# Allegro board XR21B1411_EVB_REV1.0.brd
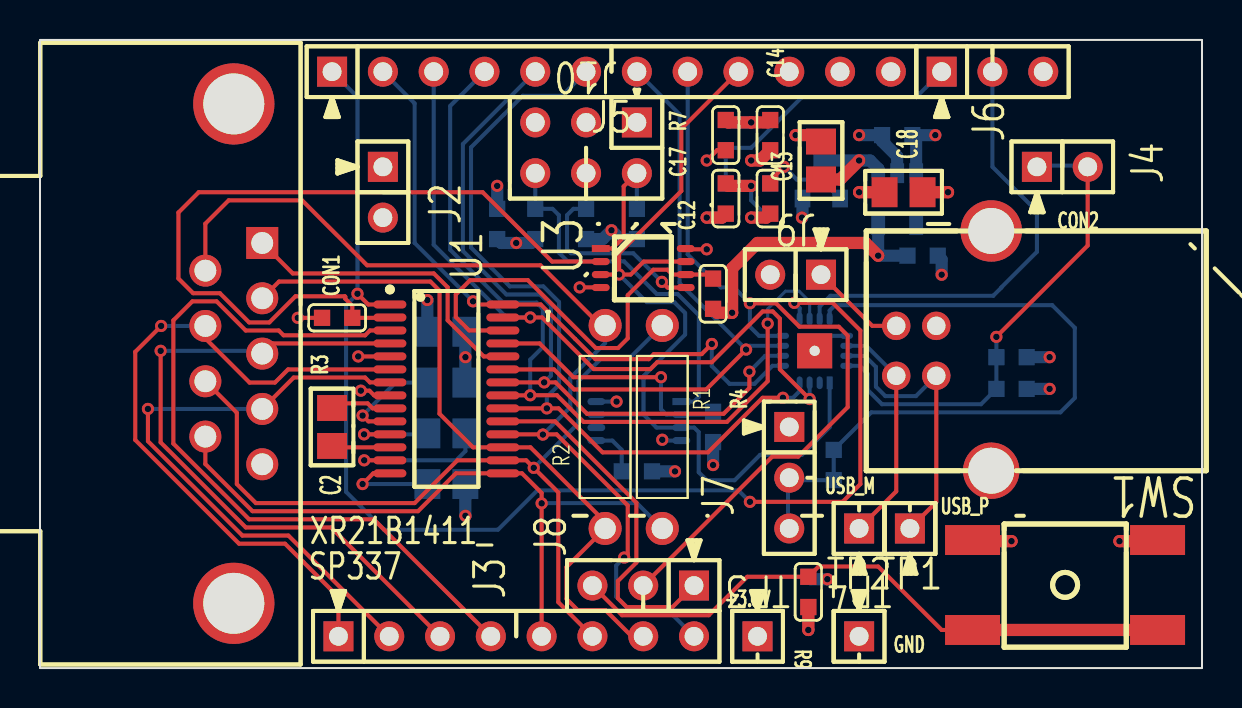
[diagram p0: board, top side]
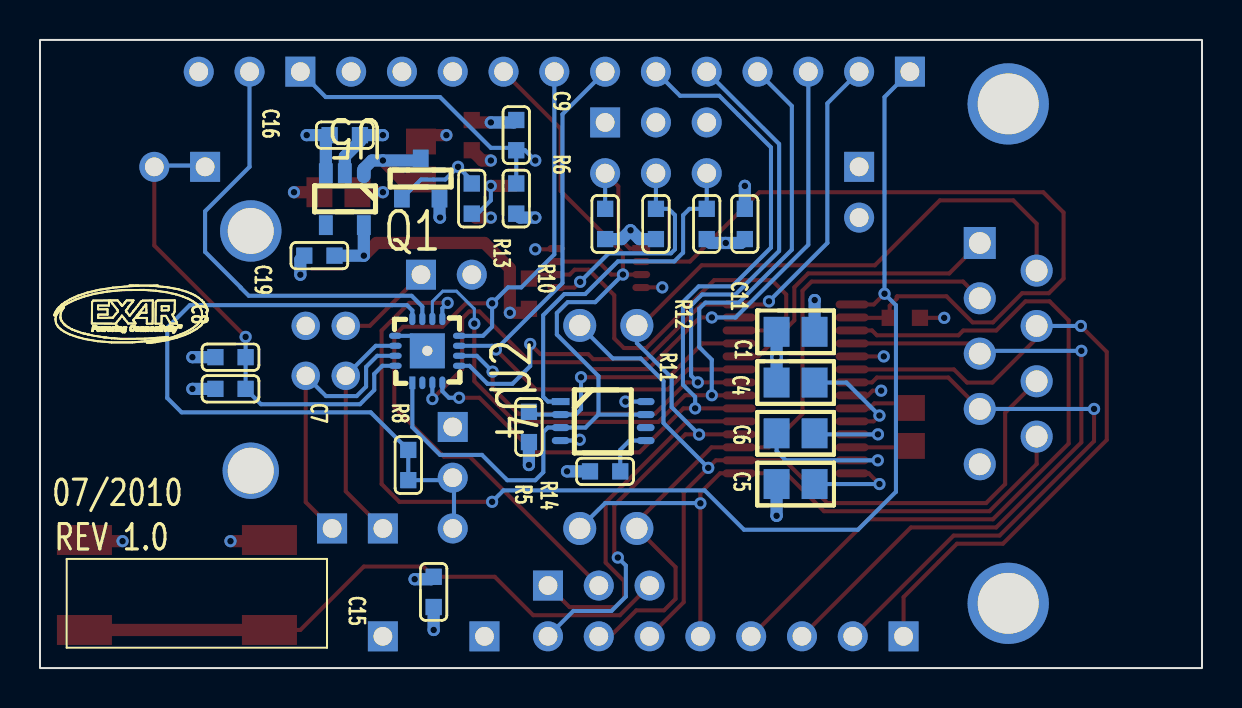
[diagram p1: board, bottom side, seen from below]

Outline 58.1 x 31.43 mm; copper layers: TOP, L2 GND, L3 PWR, BOTTOM. Coordinates in mm from the lower left corner of the outline.
Outline path: rectangle 0,0 58.1,31.43

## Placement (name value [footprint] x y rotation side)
C1  1U-0603_XXXXXX-ND  [CR0805]  20.32 16.83 180 bottom
C2  100p-0603_399-1095-1-ND  [CR0805]  14.61 12.06 90 top
C4  100p-0603_399-1095-1-ND  [CR0805]  20.32 14.29 180 bottom
C5  100p-0603_399-1095-1-ND  [CR0805]  20.32 9.21 180 bottom
C6  100p-0603_399-1095-1-ND  [CR0805]  20.32 11.75 180 bottom
C7  100n_0603_399-1095-1-ND  [CR0603]  48.58 13.97 180 bottom
C8  100n_0603_399-1095-1-ND  [CR0603]  48.58 15.56 180 bottom
C9  100n_0603_399-1095-1-ND  [CR0603]  34.29 26.67 90 bottom
C11  100n_0603_399-1095-1-ND  [CR0603]  22.86 22.23 270 bottom
C12  100n_0603_399-1095-1-ND  [CR0603]  36.51 23.5 90 top
C13  10U_0805, 10V_399-4925-1-ND  [CR0805]  39.05 25.4 90 top
C14  100n_0603_399-1095-1-ND  [CR0603]  36.51 26.67 90 top
C15  100n_0603_399-1095-1-ND  [CR0603]  38.42 3.81 270 bottom
C16  1U-0805,16V_PCC2249TR-ND  [CR0603]  42.86 26.67 0 bottom
C17  100n_0603_399-1095-1-ND  [CR0603]  34.29 23.5 90 top
C18  1U-0805,16V_PCC2249TR-ND  [CR0805]  43.18 23.81 180 top
C19  100n_0603_399-1095-1-ND  [CR0603]  44.13 20.64 0 bottom
CON1  CONNECTOR_DB9_182-709ME-ND  [DSUB9_MALE]  11.11 21.27 270 top
CON2  USB B-_A31725-ND  [USB_B_TYPE_CON_1]  43.81 15.88 90 top
J2  2x1 .1  Header_PEC02SAAN  [HDR254S3-1X2]  17.14 25.08 270 top
J3  CON2_7  [HDR254S3-1X8]  14.92 1.59 0 top
J4  2x1 .1  Header_PEC02SAAN  [HDR254S3-1X2]  49.85 25.08 0 top
J5  12x1 .1  _Header_PEC012SAAN  [HDR254S3-1X12]  14.61 29.84 0 top
J6  3x1 .1  Header_PEC03SAAN  [HDR254S3-1X3]  45.09 29.84 0 top
J7  3x1 .1  Header_PEC03SAAN  [HDR254S3-1X3]  37.47 12.06 270 top
J8  3x1 .1  Header_PEC03SAAN  [HDR254S3-1X3]  32.7 4.13 180 top
J9  2x1 .1  Header_PEC02SAAN  [HDR254S3-1X2]  39.05 19.68 180 top
J10  CON6A_PEC03DAAN  [HDR254M-2X3]  29.84 27.3 180 top
NOREF  -  []  0 31.43 0 top
NOREF#2  -  []  0 0 90 top
NOREF#3  -  []  57.4 16.26 180 bottom
Q1  SI2333DS-T1-E3-SOT-23  [SOT_23]  40.01 23.5 180 bottom
R1  120_0603  [RES400]  31.11 6.99 0 top
R2  120_0603  [RES400]  28.26 17.14 180 top
R3  470K-0603_311-470KGRCT-ND  [CR0603]  14.86 17.53 180 top
R4  470K-0603_311-470KGRCT-ND  [CR0603]  33.66 18.73 270 top
R5  470K-0603_311-470KGRCT-ND  [CR0603]  33.66 12.06 270 bottom
R6  3.3K-0603  [CR0603]  34.29 23.5 90 bottom
R7  4.7K-0603  [CR0603]  34.29 26.67 90 top
R8  ZERO-0603  [CR0603]  39.69 10.16 90 bottom
R9  47K-0603_311-47KGRCT-ND  [CR0603]  38.42 3.81 270 top
R10  47K-0603_311-47KGRCT-ND  [CR0603]  29.84 22.23 270 bottom
R11  47K-0603_311-47KGRCT-ND  [CR0603]  27.3 22.23 270 bottom
R12  47K-0603_311-47KGRCT-ND  [CR0603]  24.77 22.23 270 bottom
R13  40.2K-0603_311-40.2KGRCT-ND  [CR0603]  36.51 23.5 270 bottom
R14  47K-0603_311-47KGRCT-ND  [CR0603]  29.84 9.84 0 bottom
SW1  PB SW_101-0164-EV  [TACT_SMD_SWITCH_SWITRONICS]  55.88 1.91 180 top
TP1  PEC01SAAN  [HDR254S3-1X1]  43.5 6.99 0 top
TP2  PEC01SAAN  [HDR254S3-1X1]  40.96 6.99 0 top
TP3  PEC01SAAN  [HDR254S3-1X1]  35.88 1.59 180 top
TP4  PEC01SAAN  [HDR254S3-1X1]  40.96 1.59 180 top
U1  SP337_TSSOP  [TSSOP65MM_28P]  20.32 13.97 270 top
U2  XR21B1411IL16-QFN16  [QFN_16_3X3_MM]  38.73 15.88 90 bottom
U3  SN74LVC2G66DCT  [SSOP_8]  28.04 20.99 270 top
U4  SN74LVC2G66DCT  [SSOP_8]  32.07 13.34 270 bottom
U5  SP6260GEK-L/TR150MA  [SOT_23_5]  41.91 24.77 0 bottom

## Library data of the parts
C1 C2 C4-C9 C11-C19 = CAP NP
CON1 = CONNECTOR_DB9_0
CON2 = USB B-Type Connector
J2 J4 J9 = CON2: User Part Number: pn; Tolerance: RichardLC
J3 = CON2_7: User Part Number: pn; Tolerance: RichardLC
J5 = CON2_1: User Part Number: pn; Tolerance: RichardLC
J6-J8 = CON3: User Part Number: pn; Tolerance: RichardLC
J10 = CON6A: User Part Number: pn; Tolerance: RichardLC
Q1 = Si2333DS
R1 R2 = R_0: Tolerance: ***; User Part Number: ***; room: MASTER_CH1
R3-R5 = R_0: room: MASTER_CH1
R6-R14 = R
SW1 = SW PUSHBUTTON-SPST-2
TP1-TP4 = TP: User Part Number: pn; Tolerance: RichardLC
U1 = SP302_9: User Part Number: pn; Tolerance: RichardLC; room: MASTER_CH9
U2 = XR21V1410_7
U3 U4 = SN74LVC2G66DCT_0
U5 = SP6669_0

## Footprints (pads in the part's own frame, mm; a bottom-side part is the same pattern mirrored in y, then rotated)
CR0603
  rect 0.813x0.813 smd: 1(-0.756,0) 2(0.756,0)
CR0805
  rect 1.295x1.499 smd: 1(-0.95,0) 2(0.95,0)
DSUB9_MALE
  rect 1.6x1.6 hole 1.092: 1(0,0)
  round 1.6 hole 1.092: 2(2.769,0) 3(5.537,0) 4(8.306,0) 5(11.074,0) 6(1.384,-2.845) 7(4.153,-2.845) 8(6.921,-2.845) 9(9.69,-2.845)
  round 4.064 hole 3.048: MH1(-6.96,-1.422) MH2(18.034,-1.422)
HDR254M-2X3
  rect 1.5x1.5 hole 0.94: 1(0,0)
  round 1.5 hole 0.94: 2(0,2.54) 3(2.54,0) 4(2.54,2.54) 5(5.08,0) 6(5.08,2.54)
HDR254S3-1X1
  rect 1.5x1.5 hole 0.94: 1(0,0)
HDR254S3-1X2
  rect 1.5x1.5 hole 0.94: 1(0,0)
  round 1.5 hole 0.94: 2(2.54,0)
HDR254S3-1X3
  rect 1.5x1.5 hole 0.94: 1(0,0)
  round 1.5 hole 0.94: 2(2.54,0) 3(5.08,0)
HDR254S3-1X8
  rect 1.5x1.5 hole 0.94: 1(0,0)
  round 1.5 hole 0.94: 2(2.54,0) 3(5.08,0) 4(7.62,0) 5(10.16,0) 6(12.7,0) 7(15.24,0) 8(17.78,0)
HDR254S3-1X12
  rect 1.5x1.5 hole 0.94: 1(0,0)
  round 1.5 hole 0.94: 2(2.54,0) 3(5.08,0) 4(7.62,0) 5(10.16,0) 6(12.7,0) 7(15.24,0) 8(17.78,0) 9(20.32,0) 10(22.86,0) 11(25.4,0) 12(27.94,0)
QFN_16_3X3_MM
  rect 0.635x0.305 smd: 1(-1.6,0.749)
  oval 0.635x0.305 smd: 2(-1.6,0.249) 3(-1.6,-0.251) 4(-1.6,-0.752) 9(1.6,-0.752) 10(1.6,-0.251) 11(1.6,0.249) 12(1.6,0.749)
  oval 0.305x0.635 smd: 5(-0.749,-1.6) 6(-0.249,-1.6) 7(0.251,-1.6) 8(0.752,-1.6) 13(0.752,1.6) 14(0.251,1.6) 15(-0.249,1.6) 16(-0.749,1.6)
  rect 1.753x1.753 hole 0.508: 17(0,0)
RES400
  round 1.651 hole 1.067: 1(0,0) 2(0,10.16)
SOT_23
  rect 0.787x0.889 smd: 1(0,0) 2(1.88,0) 3(0.94,2.007)
SOT_23_5
  oval 0.691x0.991 smd: 1(0,0)
  rect 0.691x0.991 smd: 2(0.95,0) 3(1.9,0) 4(1.9,2.601) 5(0,2.601)
SSOP_8
  rect 0.356x0.889 smd: 1(0,0)
  oval 0.356x0.889 smd: 2(0.65,0) 3(1.3,0) 4(1.951,0) 5(1.951,4.249) 6(1.3,4.249) 7(0.65,4.249) 8(0,4.249)
TACT_SMD_SWITCH_SWITRONICS
  rect 2.751x1.499 smd: 1(0,0) 2(9.251,0) 3(0,-4.501) 4(9.251,-4.501)
TSSOP65MM_28P
  oval 0.4x1.65 smd: 1(-4.225,-2.825) 2(-3.575,-2.825) 3(-2.925,-2.825) 4(-2.275,-2.825) 5(-1.625,-2.825) 6(-0.975,-2.825) 7(-0.325,-2.825) 8(0.325,-2.825) 9(0.975,-2.825) 10(1.625,-2.825) 11(2.275,-2.825) 12(2.925,-2.825) 13(3.575,-2.825) 14(4.225,-2.825) 15(4.225,2.825) 16(3.575,2.825) 17(2.925,2.825) 18(2.275,2.825) 19(1.625,2.825) 20(0.975,2.825) 21(0.325,2.825) 22(-0.325,2.825) 23(-0.975,2.825) 24(-1.625,2.825) 25(-2.275,2.825) 26(-2.925,2.825) 27(-3.575,2.825) 28(-4.225,2.825)
USB_B_TYPE_CON_1
  round 1.422 hole 0.919: 1(1.25,1.001) 2(-1.25,1.001) 3(-1.25,-1.001) 4(1.25,-1.001)
  round 3.073 hole 2.299: 5(5.999,-3.749)
  round 2.819 hole 2.299: 6(-5.999,-3.749)

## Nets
+3.3V: C11.2 C15.2 C18.2 C19.1 J2.1 J7.3 R4.2 R5.2 R9.2 R10.2 R11.2 R12.2 R14.2 TP3.1 U3.8(VCC) U4.8(VCC) U5.5(VOUT)
GND: C1.1 C4.1 C5.1 C7.1 C8.1 C9.2 C11.1 C13.2 C14.2 C15.1 C16.1 C17.2 C18.1 C19.2 CON1.5 CON1.MH1 CON1.MH2 CON2.4(GND) CON2.5(SH1) CON2.6(SH2) J5.11 J5.12 J6.3 J10.1 J10.3 J10.5 R3.2 R7.2 R13.2 SW1.3 SW1.4 TP4.1 U1.8(GND) U2.13(GND_13) U2.17(E_PAD) U3.4(GND) U4.4(GND) U5.2(GND)
VBUS_SENSE: J6.2 U2.11(VBUS_SENSE)
VCC_USB: C13.1 C14.1 C16.2 C17.1 J4.1 Q1.3(D) R6.1 U5.1(VIN) U5.3(CE)
VCC_USB_VBUS: C12.1 J9.2 Q1.2(S)
CD#: J5.7 U1.23(R5_OUT) U2.7(GPIO1/CD#)
CTS: CON1.8 J3.6 R1.2 U1.16(R2_IN)
CTS#: J5.6 U1.20(R2_OUT) U2.4(GPIO4/CTS#)
DCD: CON1.1 U1.24(R5_IN)
DSR: CON1.6 J3.8 R2.1 U1.18(R4_IN)
DSR#: J5.5 U1.22(R4_OUT) U2.6(GPIO2/DSR#)
DTR: CON1.4 J3.2 U1.7(T2_OUT)
DTR#: J5.2 U1.28(T2_IN) U2.5(GPIO3/DTR#)
RD: CON1.2 J3.7 R2.2 U1.17(R3_IN)
RI: CON1.9 J3.5 R1.1 U1.15(R1_IN)
RI#: J5.8 J8.2 U2.8(GPIO0/RI#)
RS232#_RS485: R5.1 U1.25(RS232#_RS485) U4.2(1B)
RTS: CON1.7 J3.1 U1.6(T1_OUT)
RTS#: J5.3 U1.27(T1_IN) U2.3(GPIO5/RTS#)
RX: J5.4 U1.21(R3_OUT) U2.10(RX)
RX_EN#: R4.1 U1.26(RX_EN#) U3.6(2B)
SUSPEND#: J5.9 U2.1(LOWPOWER) U3.3(2C) U3.7(1C) U4.3(2C) U4.7(1C)
TD: CON1.3 J3.3 U1.4(T3_OUT)
TRANS_RI#: J8.1 U1.19(R1_OUT)
TX: J5.1 U1.1(T3_IN) U2.9(TX)
TX_EN: R3.1 U1.2(TX_EN) U3.2(1B)
USB_DM: CON2.2(DM) TP2.1 U2.14(USBD_M)
USB_DP: CON2.3(DP) TP1.1 U2.15(USBD_P)
VIO_REF: C1.2 J2.2 J5.10 J7.1 U1.5(VCC)
N17094617: J8.3 R9.1 SW1.1 SW1.2
N17260408: C7.2 C8.2 J4.2 U2.16(VCC)
N17360914: R14.1 U4.5(2A)
N17372035: J10.2 R10.1 U3.1(1A)
N17372732: J10.4 R11.1 U3.5(2A)
N17428845: CON2.1(V_BUS) J9.1
N17428937: C12.2 Q1.1(G) R13.1
N17497408: J10.6 R12.1 U4.1(1A)
N17687931: J7.2 R8.1
N17694114: C9.1 J6.1 R6.2 R7.1
N17722908: R8.2 U2.12(VIO_REF)
N17796579: J3.4 U1.3(T4_OUT)
N17796703: C4.2 U1.10(V+)
N17796705: C5.2 U1.14(V-)
N17796729: C2.2 U1.9(C1(+))
N17796733: C2.1 U1.12(C1(-))
N17796737: C6.1 U1.13(C2(-))
N17796741: C6.2 U1.11(C2(+))

Pads without a net: U2 2; U4 6; U5 4

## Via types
v1: diameter 0.61, hole 0.33, TOP to BOTTOM, 68 vias

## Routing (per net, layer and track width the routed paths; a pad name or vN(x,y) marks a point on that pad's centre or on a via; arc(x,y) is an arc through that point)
+3.3V: length 27.3
  TOP w0.203: U3.8 32.33,20.95 v1(33.34,20.95)
  TOP w0.61: v1(38.42,1.91) R9.2 ; v1(41.91,20.64) 41.27,21.27 35.88,21.27 34.61,20 v1(34.61,17.78) 33.85,17.78 R4.2 ; C18.2 v1(40.96,23.81)
  BOTTOM w0.203: U4.8 v1(28.83,13.34)
  BOTTOM w0.61: R10.2 29.01,21.47 v1(28.57,21.91) 28.14,21.47 R11.2 ; U5.5 v1(41.91,20.64) C19.1 ; C11.2 23.06,21.27 v1(23.81,21.27) 24.57,21.27 R12.2 ; v1(31.75,9.84) R14.2 ; v1(38.42,1.91) R9.2 ; R5.2 v1(33.66,10.16)
GND: length 33.2
  TOP w0.203: R3.2 v1(12.89,17.53) ; U3.4 28.03,19.05 v1(26.99,19.05) ; U1.8 16.71,13.64 16.47,13.88 v1(16.04,13.88)
  TOP w0.61: SW1.4 46.69,6.35 v1(48.58,6.35) ; R7.2 34.41,27.3 v1(35.56,27.3) 36.39,27.3 C14.2 ; v1(53.98,6.35) 55.82,6.35 SW1.3 ; C17.2 34.41,24.13 v1(35.56,24.13) ; v1(45.4,23.81) C18.1 ; v1(37.78,26.67) 38.73,26.67 C13.2
  BOTTOM w0.203: v1(35.56,24.13) 35.56,23.4 36.23,22.74 R13.2 ; U2.13 39.49,16.63 U2.17 ; v1(31.11,11.42) 31.16,11.38 U4.4
  BOTTOM w0.61: R7.2 34.41,27.3 v1(35.56,27.3) ; C4.1 21.27,15.55 v1(21.27,15.56) 21.27,15.56 C1.1 ; v1(50.48,15.56) C8.1 ; C15.1 38.54,4.45 v1(39.37,4.45) ; v1(21.27,7.62) 21.27,7.62 C5.1 ; v1(45.09,19.68) 45.09,20.44 C19.2 ; v1(40.96,26.67) C16.1 42.11,26.36 42.86,25.61 U5.2 ; v1(22.86,24.13) C11.1 ; v1(50.48,13.97) C7.1
VBUS_SENSE: length 22.6
  BOTTOM w0.203: U2.11 38.98,18.09 39.52,18.63 47.66,18.63 48.07,19.04 48.07,19.05 49.85,20.83 49.85,22.86 47.62,25.08 J6.2
VCC_USB: length 11.9
  TOP w0.61: C14.1 36,25.4 v1(35.56,25.4) ; C13.1 40.01,24.45 v1(40.96,25.4) ; C17.1 34.09,22.54 v1(33.34,22.54)
  BOTTOM w0.61: U5.3 43.81,26.48 C16.2 v1(44.77,26.67) ; Q1.3 39.17,25.4 v1(40.96,25.4) 41.5,25.4 41.91,24.99 U5.1 ; C17.1 34.09,22.54 v1(33.34,22.54)
VCC_USB_VBUS: length 2
  TOP w0.61: C12.1 36.32,22.54 v1(35.56,22.54)
  BOTTOM w0.61: Q1.2 38.13,22.57 v1(38.1,22.54)
CD#: length 31.5
  TOP w0.203: v1(35.31,15.94) 33.31,13.94 26.71,13.94 25.7,14.95 U1.23
  BOTTOM w0.203: J5.7 31.98,27.71 31.98,19.27 v1(35.31,15.94) 35.49,16.13 U2.7
CTS: length 42.3
  TOP w0.203: CON1.8 9.84,12.78 9.84,9.21 10.79,8.26 18.73,8.26 20.87,10.39 U1.16 24.31,10.39 v1(24.69,10.02) 25.92,8.79 25.92,3.29 J3.6
  BOTTOM w0.203: v1(24.69,10.02) 26.92,12.26 26.92,14.35 28.06,15.49 29.46,15.49 R1.2
CTS#: length 40.9
  TOP w0.203: U1.20 v1(25.34,12.99) 25.93,12.99 28.13,10.79 33.4,10.79 36.13,13.53 v1(37.15,13.53)
  BOTTOM w0.203: U2.4 37.98,13.85 37.66,13.53 v1(37.15,13.53) ; J5.6 26.1,28.64 24.13,28.64 23.18,27.68 21.55,26.06 21.55,21.04 23.49,19.1 25.17,19.1 25.95,18.31 25.95,14.18 25.34,13.57 v1(25.34,12.99)
DCD: length 15.4
  TOP w0.203: U1.24 22.19,15.6 20.38,17.4 20.38,19.05 19.69,19.75 12.64,19.75 CON1.1
DSR: length 49.4
  TOP w0.203: CON1.6 8.27,22.24 9.44,23.41 13.11,23.41 16.36,20.15 25.02,20.15 28.03,17.14 R2.1 ; 25.14,11.69 v1(25.15,11.68) ; 25.14,11.69 25.83,11.69 29.39,8.14 29.39,5.71 v1(29.21,5.53) ; 25.14,11.69 U1.18
  BOTTOM w0.203: v1(25.15,11.68) 26.52,13.06 26.52,14.52 28.26,16.26 R2.1 ; v1(29.21,5.53) 28.81,5.13 28.81,3.58 29.53,2.86 31.43,2.86 J3.8
DSR#: length 36.3
  TOP w0.203: U1.22 v1(25.21,14.3) 25.78,14.3 27.35,12.73 34.18,12.73 35.47,14.01 v1(35.47,14.83)
  BOTTOM w0.203: v1(35.47,14.83) 36.26,15.63 U2.6 ; v1(25.21,14.3) 25.55,14.63 25.55,18.14 25,18.69 23.32,18.69 21.15,20.87 21.15,26.23 J5.5
DTR: length 30.6
  TOP w0.203: v1(5.4,12.97) 5.4,11.35 10.12,6.63 12.42,6.63 J3.2 ; U1.7 16.5,14.3 16.26,14.54 12.68,14.54 CON1.4
  BOTTOM w0.203: v1(5.4,12.97) CON1.4
DTR#: length 32.2
  TOP w0.203: v1(33.59,16.22) 33.08,15.71 30.69,15.71 30.44,15.46 27.77,15.46 26.76,16.47 25.03,18.2 U1.28 21.81,18.2 v1(21.65,18.35)
  BOTTOM w0.203: U2.5 36.63,15.13 35.72,14.22 34.48,14.22 33.59,15.11 v1(33.59,16.22) ; J5.2 18.73,28.26 18.73,21.27 v1(21.65,18.35)
RD: length 35.4
  TOP w0.203: CON1.2 11.95,19.34 19.52,19.34 19.98,18.88 19.98,12.73 21.66,11.04 U1.17 24.53,11.04 28.26,7.31 28.26,6.99 R2.2 26.32,5.05 26.32,3.46 26.9,2.89 28.29,2.89 29.59,1.59 J3.7
RI: length 34.1
  TOP w0.203: J3.5 v1(25.08,8.24) 25.08,8.76 24.1,9.74 U1.15 20.8,9.74 18.9,7.85 10.63,7.85 8.27,10.21 CON1.9
  BOTTOM w0.203: v1(25.08,8.24) 25.1,8.26 29.84,8.26 R1.1
RI#: length 39.3
  TOP w0.203: J8.2 36.61,10.58 37.91,10.58 40.39,13.05 40.39,16.64 39.94,17.08 37.98,17.08 36.81,18.25 v1(35.5,18.25)
  BOTTOM w0.203: 32.38,29.84 32.38,20.7 34.04,19.05 34.7,19.05 v1(35.5,18.25) 35.5,17.08 35.95,16.63 U2.8
RS232#_RS485: length 13
  TOP w0.203: U1.25 24.98,16.25 26.67,14.55 v1(31.05,14.55)
  BOTTOM w0.203: v1(31.05,14.55) 31.05,12.96 31.32,12.68 U4.2 33.52,12.68 R5.1
RTS: length 34.9
  TOP w0.203: v1(6.06,17.12) 4.76,15.82 4.76,11.41 9.95,6.22 12.25,6.22 13.18,5.3 14.92,3.55 J3.1 ; CON1.7 8.27,16.5 10.48,14.29 11.75,14.29 12.41,14.95 U1.6
  BOTTOM w0.203: v1(6.06,17.12) CON1.7
RTS#: length 36.7
  TOP w0.203: v1(38.48,13.46) 37,14.95 37,17.49 36.64,17.85 36.13,17.85 33.59,15.3 30.86,15.3 30.52,14.96 27.69,14.96 27.33,15.32 25.11,17.55 v1(24.51,17.55) U1.27
  BOTTOM w0.203: 19.68,29.84 19.68,21.18 23.32,17.55 v1(24.51,17.55) ; U2.3 v1(38.48,13.46)
RX: length 41.9
  TOP w0.203: v1(36.39,17.24) 36.39,14.35 34.35,12.32 27.18,12.32 25.85,13.65 v1(24.51,13.65) 24.5,13.64 U1.21
  BOTTOM w0.152: U2.10 38.48,18.34 37.96,18.86 37.27,18.86 36.39,17.97 v1(36.39,17.24)
  BOTTOM w0.203: v1(24.51,13.65) 24.51,15.43 25.14,16.06 25.14,17.98 24.83,18.29 23.15,18.29 20.51,20.93 20.51,28.13 J5.4
RX_EN#: length 21.4
  TOP w0.203: U1.26 21.46,16.9 20.79,17.57 20.79,18.69 21.51,19.41 24.39,19.41 27.79,16.01 28.91,16.01 29.39,16.5 29.39,18.66 30.67,19.94 31.37,19.94 31.62,19.69 U3.6 33.45,19.69 R4.1
SUSPEND#: length 44.7
  TOP w0.203: U3.7 30.19,20.34 29.54,19.69 v1(28.96,19.69) ; v1(28.96,19.69) U3.3 ; v1(28.96,19.69) 28.96,20.76 32.07,23.87 32.07,26.99 J5.9
  BOTTOM w0.203: v1(28.96,19.69) 30.34,18.31 31.71,18.31 32.26,17.77 32.26,16.69 30.18,14.61 30.18,12.68 ; U4.7 30.18,12.68 ; 30.18,12.68 30.83,12.03 U4.3 32.71,12.03 32.94,11.81 32.94,9.8 33.34,9.4 34.73,9.4 36,10.67 38.1,10.67 39.48,12.05 U2.1
TD: length 34.3
  TOP w0.203: CON1.3 11.62,16.25 U1.4 ; v1(6.03,15.88) 6.03,11.29 10.29,7.04 14.55,7.04 J3.3
  BOTTOM w0.203: v1(6.03,15.88) 10.97,15.88 CON1.3
TRANS_RI#: length 18
  TOP w0.203: J8.1 31.62,3.05 29.34,3.05 28.89,3.49 28.89,4.19 28.89,4.35 29.82,5.28 29.82,8.28 25.76,12.34 U1.19
TX: length 64
  TOP w0.203: v1(15.88,18.73) 16.41,18.2 U1.1 ; v1(35.5,8.32) 40.13,8.32 41.02,9.21 41.02,16.89 39.64,18.28 v1(37.72,18.28)
  BOTTOM w0.203: J5.1 15.88,28.57 v1(15.88,18.73) 15.3,18.16 15.3,8.82 17.2,6.92 22.9,6.92 24.87,8.89 34.92,8.89 v1(35.5,8.32) ; v1(37.72,18.28) 37.98,18.01 U2.9
TX_EN: length 39.2
  TOP w0.203: U3.2 25.6,20.34 22.13,23.81 7.94,23.81 6.92,22.8 6.92,19.49 7.66,18.76 9,18.76 10.46,17.3 11.47,17.3 12.78,18.61 15.24,18.61 15.27,18.58 15.27,18.48 15.62,18.13 R3.1 17.48,17.53 U1.2
USB_DM: length 11.5
  TOP w0.203: CON2.2 42.81,8.84 TP2.1
  BOTTOM w0.203: U2.14 41.31,16.13 CON2.2
USB_DP: length 14.5
  TOP w0.203: TP1.1 44.82,8.3 CON2.3
  BOTTOM w0.203: CON2.3 43.8,13.61 42.27,13.61 41.8,14.08 41.8,15.07 41.24,15.63 U2.15
VIO_REF: length 3.2
  TOP w0.203: U1.5 v1(15.91,15.6)
  BOTTOM w0.61: v1(19.37,18.41) 19.37,18.41 C1.2
N17094617: length 31.2
  TOP w0.203: 46.63,1.91 45.09,1.91 41.91,5.08 38.93,5.08 R9.1 35.36,4.57 33.44,2.64 29.11,2.64 J8.3
  TOP w0.61: 46.63,1.91 SW1.1
N17260408: length 22.1
  TOP w0.203: v1(47.82,16.57) 47.82,16.58 52.39,21.15 J4.2
  BOTTOM w0.203: v1(47.82,16.57) C8.2 C7.2 47.05,13.2 42.1,13.2 41.39,13.91 41.39,14.72 40.99,15.13 U2.16
N17360914: length 2.5
  BOTTOM w0.203: R14.1 29.09,10.92 28.62,11.38 U4.5
N17372035: length 6.6
  TOP w0.203: U3.1 28.61,20.99 29.18,21.56 29.18,24.1 J10.2
  BOTTOM w0.203: J10.2 R10.1
N17372732: length 11.3
  TOP w0.203: U3.5 31.38,19.04 v1(31.1,19.33)
  BOTTOM w0.203: J10.4 R11.1 26.67,22.98 26.35,22.66 26.35,20.96 26.55,20.76 29.66,20.76 v1(31.1,19.33)
N17428845: length 4.8
  TOP w0.203: J9.1 41.61,17.12 CON2.1
N17428937: length 5.7
  TOP w0.203: v1(37.2,25.08) 36.51,24.4 C12.2
  BOTTOM w0.203: C12.2 36.51,24.4 v1(37.2,25.08) 37.84,24.45 38.42,24.45 39.05,24.45 Q1.1
N17497408: length 18.3
  BOTTOM w0.203: J10.6 R12.1 25.63,22.98 25.95,22.66 25.95,20.79 26.38,20.35 29.21,20.35 30.84,18.72 31.88,18.72 32.94,17.66 32.94,13.58 32.7,13.34 U4.1
N17687931: length 2.3
  BOTTOM w0.203: R8.1 37.59,9.4 J7.2
N17694114: length 16.4
  TOP w0.203: R7.1 33.85,25.91 v1(33.34,25.4)
  BOTTOM w0.203: v1(33.34,25.4) 33.85,25.91 R7.1 ; R6.2 R7.1 ; R7.1 34.41,26.04 35.56,26.04 38.1,28.57 43.81,28.57 J6.1
N17722908: length 29.9
  BOTTOM w0.203: R8.2 41.57,12.8 51.02,12.8 51.74,13.52 51.74,17.03 50.61,18.16 40.51,18.16 39.75,18.16 39.48,17.89 U2.12
N17796579: length 38.1
  TOP w0.203: J3.4 16.69,7.44 10.46,7.44 6.67,11.23 6.67,17.4 7.62,18.35 8.83,18.35 10.29,16.89 11.94,16.89 12.18,16.65 16.26,16.65 16.5,16.9 U1.3
N17796703: length 5.4
  TOP w0.203: U1.10 16.42,12.34 v1(16.13,12.64)
  BOTTOM w0.203: C4.2 17.78,14.29 v1(16.13,12.64)
N17796705: length 4.8
  TOP w0.203: U1.14 16.67,9.74 v1(16.13,9.21)
  BOTTOM w0.203: C5.2 v1(16.13,9.21)
N17796729: length 3.1
  TOP w0.203: U1.9 16.63,12.99 16.38,13.25 14.84,13.25 C2.2
N17796733: length 2.9
  TOP w0.203: U1.12 14.68,11.04 C2.1
N17796737: length 7.4
  TOP w0.203: v1(16.21,10.39) U1.13
  BOTTOM w0.203: v1(16.21,10.39) 20.81,10.39 21.27,10.86 C6.1
N17796741: length 4.5
  TOP w0.203: v1(16.2,11.69) U1.11
  BOTTOM w0.203: C6.2 19.32,11.69 v1(16.2,11.69)

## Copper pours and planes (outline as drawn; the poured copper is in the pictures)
+3.3V on L3 PWR: 20.64,13.97 20.64,20.32 19.05,20.32 19.05,24.13 15.24,24.13 15.24,26.99 30.48,26.99 30.48,21.27 33.66,21.27 33.66,18.1 35.88,18.1 35.88,10.79 56.83,10.79 56.83,1.27 1.27,1.27 1.27,13.97
+3.3V on L3 PWR: 40.64,24.13 40.64,18.73 44.13,18.73 44.13,24.13
GND on L2 GND: 1.27,1.27 1.27,30.16 56.83,30.16 56.83,1.27
VCC_USB on L3 PWR: 31.11,21.91 31.11,26.99 51.75,26.99 51.75,18.73 44.77,18.73 44.77,24.77 40.01,24.77 40.01,24.13 33.66,24.13 33.66,21.91
VCC_USB_VBUS on L3 PWR: 34.29,23.5 34.29,18.73 40.01,18.73 40.01,23.5
VIO_REF on L3 PWR: 36.51,11.43 36.51,18.1 52.39,18.1 52.39,27.62 14.61,27.62 14.61,23.5 18.41,23.5 18.41,19.37 20,19.37 20,14.61 1.27,14.61 1.27,30.16 56.83,30.16 56.83,11.43

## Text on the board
Ref Des/Silkscreen Bottom: REV 1.0 | 07/2010
Ref Des/Silkscreen Top: +3.3V | USB_M | GND | USB_P | SP337 | XR21B1411_ | TxD | 29 | TxCE | ST | 30 | RS(A) | RTS | 83 | 85 | RS(B) | 31 | 75 | TR(A) | DTR | 78 | 32 | TR(B) | 81 | 33 | RRC(A) | DCD_DCE | 79 | RRC(B) | 34 | RL | 65 | RL(A) | 63 | LL(A) | D0 | D1 | 0 | 1 | EIA-530A | RS-449(V.36) | X.21 (V.11) | SHUTDOWN | 2 | 3 | +VSS | 4 | Gnd | 5 | 6 | 7 | 8 | ST(B) | ST(A) | 12 | 15 | TxC(A) | CSEN | 10
DIMENSION: LAYER CONSTRUCTION | LAYER1 TOP | LAYER2 GND | LAYER3 PWR | LAYER4 BOTTOM | MATERIAL: FR4 | PLATING: SMOBC | MASK: LPI | MASK COLOR: RED | PCB THICKNESS: 62 MILS +-5
DISPLAY_TOP: FIGURE | SIZE | 13.0 | 20.0 | 36.2 | 37.01 | 42.0 | 43.0 | 90.5 | 120.0 | DRILL CHART: TOP to BOTTOM | ALL UNITS ARE IN MILS | TOLERANCE | +2.0/-2.0 | +3.0/-3.0 | PLATED | QTY | 68 | 1 | 4 | 45 | 9 | 2
COMPVAL_TYPE_TOP: VIO_REF | N17396031 | +5V
